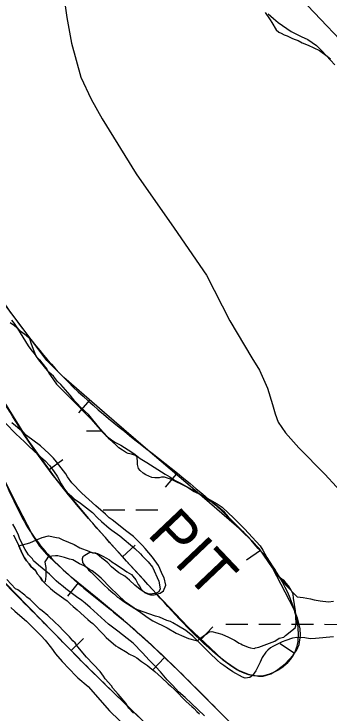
# Model space of a CAD drawing. Extents: x 3161665 to 3199565, y 885729 to 911164.
# Drawn here: x 3169915 to 3170375, y 908095 to 909117 of the extents above; entities that cross this region are included whole.
import ezdxf

# ---------------------------------------------------------------- set-up
doc = ezdxf.new("R2010")
doc.units = 0
for name, color, linetype in [('V-BORW-IDEN', 7, 'Continuous'), ('V-BORW-LINE', 7, 'Continuous'), ('V-ROAD-CNTR', 7, 'Continuous'), ('V-SITE-VEGE', 7, 'Continuous'), ('V-TOPO-SHOR', 7, 'Continuous'), ('V-WETL-SWMP', 7, 'Continuous')]:
    doc.layers.add(name, color=color, linetype=linetype)

msp = doc.modelspace()

# ---------------------------------------------------------------- linework, layer by layer
at = {"layer": 'V-BORW-LINE'}
for p, q in [((3170025.5, 908552.9), (3170009.1, 908534)), ((3169966.1, 908451.2), (3169986.3, 908465.8)), ((3170151.8, 908444.4), (3170135.6, 908425.4)), ((3170073.3, 908323.8), (3170091.7, 908340.7)), ((3170275.4, 908332.9), (3170254.7, 908318.9)), ((3170008.8, 908285.5), (3169993, 908266.1)), ((3170188.2, 908203.2), (3170205.3, 908221.5)), ((3169998.5, 908186.7), (3170016.3, 908204.3)), ((3170324.8, 908182.7), (3170304.1, 908196.8)), ((3170134.8, 908176.6), (3170117.6, 908158.4))]:
    msp.add_line(p, q, dxfattribs=at)
for points in [[(3170090.7, 909372.3), (3170106.4, 909355.4), (3170208.1, 909263.5), (3170306.2, 909169.4), (3170400.7, 909069.3), (3170470.9, 908965.6), (3170500.1, 908886.5)], [(3169901, 908549.2), (3169935.1, 908494), (3169977.4, 908435.4), (3170023.8, 908379.7), (3170072.8, 908324.3), (3170122.9, 908269.7), (3170169.1, 908221.2), (3170219.3, 908174), (3170231.7, 908164.7), (3170241.7, 908158.8), (3170257.1, 908152.4), (3170272.3, 908149.3), (3170278.9, 908149.4), (3170290.4, 908152.7), (3170298.8, 908157.4), (3170311.1, 908167.4), (3170322.9, 908179.9), (3170328.4, 908188), (3170331.5, 908195.5), (3170333.7, 908208.9), (3170333.1, 908219.1), (3170329.4, 908234), (3170323.7, 908247.7), (3170292.7, 908307.4), (3170273.8, 908335.2), (3170251, 908359.3), (3170179.1, 908421), (3170107.2, 908482.6), (3170047.2, 908534.1), (3169987.5, 908585.8), (3169962.6, 908610.7), (3169899.1, 908695.8)], [(3169635, 908635.7), (3169645.9, 908625.6), (3169656.9, 908615.4), (3169668.2, 908605.1), (3169679.4, 908594.8), (3169697.4, 908577), (3169714.8, 908558.7), (3169739.7, 908532.5), (3169763.2, 908505), (3169772.3, 908492), (3169794.6, 908450.3), (3169809, 908417.4), (3169823.9, 908384.8), (3169847.6, 908347.3), (3169875.7, 908313.1), (3169915.5, 908271.5), (3169955.7, 908230.2), (3169986.3, 908199.1), (3170017, 908168), (3170050, 908135.4), (3170083.4, 908103.1), (3170115.9, 908072)], [(3170236.6, 908075.6), (3170196, 908116.3), (3170155.4, 908157.1), (3170115.6, 908194.7), (3170074.8, 908231.2), (3170036.7, 908262.8), (3169998.2, 908294.1), (3169966.6, 908323.2), (3169952.6, 908339.2), (3169941.1, 908357), (3169920.6, 908396.4), (3169900.6, 908435.9)]]:
    msp.add_lwpolyline(points, dxfattribs=at)
msp.add_spline([(3169635, 908635.7), (3169656.9, 908615.4), (3169679.4, 908594.8), (3169714.8, 908558.7), (3169763.2, 908505), (3169794.6, 908450.3), (3169823.9, 908384.8), (3169875.7, 908313.1), (3169955.7, 908230.2), (3170017, 908168), (3170083.4, 908103.1), (3170148.4, 908040.9), (3170215.5, 907977.3), (3170279.4, 907917), (3170341.2, 907854.9), (3170400, 907770.9), (3170439.7, 907739.9), (3170508, 907690.1), (3170580.2, 907629.1), (3170645.4, 907571.8), (3170693.9, 907538.7), (3170708.2, 907548.5), (3170700.2, 907583.3), (3170658.1, 907634.1), (3170568.8, 907738.5), (3170460.8, 907856), (3170334.8, 907977.7), (3170236.6, 908075.6), (3170155.4, 908157.1), (3170074.8, 908231.2), (3169998.2, 908294.1), (3169941.1, 908357), (3169900.6, 908435.9), (3169854.3, 908528.6), (3169775.9, 908625.5), (3169707.6, 908700.2), (3169633.3, 908764.3), (3169562.8, 908823.2), (3169485.6, 908895.1), (3169433.8, 908951), (3169435, 908964.9), (3169466.6, 908949.7), (3169508.6, 908923.8), (3169592.2, 908864.6), (3169670.7, 908813.1), (3169732.3, 908792), (3169797.1, 908714.7), (3169867.2, 908604.4), (3169935.1, 908494), (3170023.8, 908379.7), (3170122.9, 908269.7), (3170219.3, 908174), (3170272.3, 908149.3), (3170322.9, 908179.9), (3170323.7, 908247.7), (3170251, 908359.3), (3170107.2, 908482.6), (3169987.5, 908585.8), (3169899.1, 908695.8), (3169830.3, 908793), (3169752.2, 908876.5), (3169658.4, 908949.8), (3169561.7, 909020), (3169502.5, 909070.4), (3169499.7, 909114.4), (3169564.7, 909165.2), (3169544.8, 909257.9), (3169487.8, 909300.9), (3169431.9, 909310.7), (3169381.8, 909274.8), (3169352.5, 909222.6), (3169310.5, 909208.1), (3169265.3, 909228.8), (3169246.1, 909212.1), (3169266.8, 909167.6), (3169325.2, 909091.6), (3169339.4, 909049), (3169296.2, 909043.8), (3169280, 909045.3), (3169313.9, 908970.3), (3169431.9, 908841.3), (3169538.1, 908732.9), (3169635, 908635.7)], degree=3, dxfattribs=at)
at = {"layer": 'V-ROAD-CNTR'}
msp.add_lwpolyline([(3169984.6, 909162.9), (3169991.9, 909111.8), (3169998.9, 909074.4), (3170012.3, 909024.4), (3170027.5, 908992.4), (3170043.7, 908963.8), (3170093.2, 908883.5), (3170149, 908804), (3170196.1, 908735.4), (3170230.3, 908668.6), (3170262.7, 908614.3), (3170273.8, 908596.7), (3170285.2, 908570.3), (3170292.5, 908546.3), (3170296.6, 908532.5), (3170300.9, 908520.7), (3170311.8, 908505.1), (3170331.4, 908482.8), (3170369.3, 908444.5), (3170403.3, 908407.6)], dxfattribs=at)
at = {"layer": 'V-SITE-VEGE'}
for p, q in [((3170286.4, 909117.2), (3170294.2, 909110.5)), ((3170294.2, 909110.5), (3170300.9, 909104.3)), ((3170300.9, 909104.3), (3170320, 909091.5)), ((3170320, 909091.5), (3170334.5, 909084.3)), ((3170334.5, 909084.3), (3170344.3, 909079.6)), ((3170344.3, 909079.6), (3170357.2, 909070.9)), ((3170357.2, 909070.9), (3170360.8, 909066.8)), ((3170360.8, 909066.8), (3170365, 909063.1)), ((3170365, 909063.1), (3170384.1, 909042.5)), ((3169915.3, 908661.3), (3169909.1, 908665.6)), ((3169920.6, 908656.9), (3169915.3, 908661.3)), ((3169925.4, 908652.6), (3169920.6, 908656.9)), ((3169932.5, 908647.2), (3169925.4, 908652.6)), ((3169937.8, 908642.4), (3169932.5, 908647.2)), ((3169940.1, 908634.7), (3169937.8, 908642.4)), ((3169946.7, 908617.9), (3169940.1, 908634.7)), ((3169951, 908611.7), (3169946.7, 908617.9)), ((3169965.8, 908593.8), (3169951, 908611.7)), ((3169972.5, 908587.5), (3169965.8, 908593.8)), ((3169978.2, 908579.8), (3169972.5, 908587.5)), ((3169983, 908575.5), (3169978.2, 908579.8)), ((3169996.8, 908560.1), (3169983, 908575.5)), ((3170003.9, 908551.4), (3169996.8, 908560.1)), ((3170006.8, 908548.5), (3170003.9, 908551.4)), ((3170012.5, 908541.8), (3170006.8, 908548.5)), ((3170024, 908531.1), (3170012.5, 908541.8)), ((3170030.2, 908523.9), (3170024, 908531.1)), ((3170040.6, 908510.9), (3170030.2, 908523.9)), ((3169902.1, 908518.9), (3169917.3, 908503.4)), ((3170051.6, 908499.3), (3170040.6, 908510.9)), ((3169917.3, 908503.4), (3169930.2, 908491.9)), ((3169930.2, 908491.9), (3169935.5, 908486.5)), ((3170054.5, 908495.5), (3170051.6, 908499.3)), ((3170063.5, 908487.3), (3170054.5, 908495.5)), ((3169935.5, 908486.5), (3169944, 908478.3)), ((3170067.8, 908482.9), (3170063.5, 908487.3)), ((3170073.6, 908479.5), (3170067.8, 908482.9)), ((3170079.3, 908475.7), (3170073.6, 908479.5)), ((3169944, 908478.3), (3169954.1, 908469.2)), ((3169954.1, 908469.2), (3169960.3, 908463.9)), ((3170081.7, 908474.7), (3170079.3, 908475.7)), ((3170086.5, 908473.7), (3170081.7, 908474.7)), ((3170092.2, 908471.8), (3170086.5, 908473.7)), ((3170094.6, 908469.4), (3170092.2, 908471.8)), ((3170095.5, 908462.2), (3170094.6, 908469.4)), ((3169960.3, 908463.9), (3169966.5, 908457.1)), ((3170095.5, 908458.8), (3170095.5, 908462.2)), ((3169966.5, 908457.1), (3169970.8, 908451.3)), ((3169970.8, 908451.3), (3169976.9, 908443.1)), ((3170096.9, 908453), (3170095.5, 908458.8)), ((3170099.3, 908450.1), (3170096.9, 908453)), ((3170103.6, 908445.8), (3170099.3, 908450.1)), ((3169976.9, 908443.1), (3169978.4, 908440.7)), ((3169978.4, 908440.7), (3169983.6, 908430.6)), ((3170107.4, 908443.4), (3170103.6, 908445.8)), ((3170116.5, 908439.5), (3170107.4, 908443.4)), ((3170120.8, 908439), (3170116.5, 908439.5)), ((3170127.1, 908439), (3170120.8, 908439)), ((3170130.4, 908439.9), (3170127.1, 908439)), ((3170134.7, 908439.9), (3170130.4, 908439.9)), ((3170144.8, 908436.9), (3170134.7, 908439.9)), ((3169983.6, 908430.6), (3169988.8, 908422.5)), ((3170166.8, 908425.8), (3170144.8, 908436.9)), ((3169988.8, 908422.5), (3169992.6, 908417.6)), ((3170174, 908421.4), (3170166.8, 908425.8)), ((3170177.3, 908419), (3170174, 908421.4)), ((3170185, 908415.6), (3170177.3, 908419)), ((3169992.6, 908417.6), (3169998.8, 908412.3)), ((3169998.8, 908412.3), (3170002.7, 908408.5)), ((3170002.7, 908408.5), (3170012.2, 908402.2)), ((3170192.6, 908410.3), (3170185, 908415.6)), ((3170206.5, 908402.1), (3170192.6, 908410.3)), ((3170012.2, 908402.2), (3170029.4, 908388.7)), ((3170222.7, 908389), (3170206.5, 908402.1)), ((3170029.4, 908388.7), (3170037, 908380.5)), ((3170226, 908385.2), (3170222.7, 908389)), ((3170037, 908380.5), (3170042.8, 908375.2)), ((3170231.3, 908378.4), (3170226, 908385.2)), ((3170232.7, 908376), (3170231.3, 908378.4)), ((3169916.6, 908365.8), (3169913.2, 908371.6)), ((3170042.8, 908375.2), (3170053.7, 908365.5)), ((3170239.9, 908369.3), (3170232.7, 908376)), ((3170248, 908361.1), (3170239.9, 908369.3)), ((3169921.3, 908355.2), (3169916.6, 908365.8)), ((3170053.7, 908365.5), (3170057.6, 908362.6)), ((3170057.6, 908362.6), (3170069.5, 908354.4)), ((3170261.3, 908348), (3170248, 908361.1)), ((3169923.2, 908349.4), (3169921.3, 908355.2)), ((3169931.3, 908334.5), (3169923.2, 908349.4)), ((3170069.5, 908354.4), (3170091.5, 908336)), ((3170266.1, 908342.7), (3170261.3, 908348)), ((3170271.8, 908336), (3170266.1, 908342.7)), ((3169936, 908326.8), (3169931.3, 908334.5)), ((3169941.7, 908320.6), (3169936, 908326.8)), ((3170025.7, 908330.2), (3170018.5, 908325.9)), ((3170033.9, 908329.2), (3170025.7, 908330.2)), ((3170036.3, 908327.7), (3170033.9, 908329.2)), ((3170043.4, 908321.9), (3170036.3, 908327.7)), ((3170091.5, 908336), (3170099.6, 908328.3)), ((3170099.6, 908328.3), (3170102, 908325.4)), ((3170283.3, 908324.4), (3170271.8, 908336)), ((3169943.2, 908318.1), (3169941.7, 908320.6)), ((3169950.8, 908311.4), (3169943.2, 908318.1)), ((3170015.6, 908323.5), (3170014.6, 908320.6)), ((3170014.6, 908320.6), (3170015.1, 908315.3)), ((3170018.5, 908325.9), (3170015.6, 908323.5)), ((3170049.2, 908317.6), (3170043.4, 908321.9)), ((3170052, 908315.1), (3170049.2, 908317.6)), ((3170102, 908325.4), (3170111, 908316.3)), ((3170111, 908316.3), (3170117.2, 908308.5)), ((3170293.3, 908308.5), (3170283.3, 908324.4)), ((3169966.5, 908298.4), (3169950.8, 908311.4)), ((3170015.1, 908315.3), (3170016.5, 908313.4)), ((3170016.5, 908313.4), (3170020.8, 908308.6)), ((3170020.8, 908308.6), (3170023.7, 908304.7)), ((3170057.3, 908308.9), (3170052, 908315.1)), ((3170068.2, 908300.2), (3170057.3, 908308.9)), ((3170117.2, 908308.5), (3170126.7, 908288.3)), ((3170294.7, 908306.1), (3170293.3, 908308.5)), ((3170297, 908301.3), (3170294.7, 908306.1)), ((3169976.6, 908288.7), (3169966.5, 908298.4)), ((3170023.7, 908304.7), (3170027.5, 908301.4)), ((3170027.5, 908301.4), (3170038.5, 908290.8)), ((3170076.9, 908295.3), (3170068.2, 908300.2)), ((3170299.9, 908297), (3170297, 908301.3)), ((3170301.8, 908294.6), (3170299.9, 908297)), ((3169980.4, 908285.3), (3169976.6, 908288.7)), ((3169986.6, 908280.5), (3169980.4, 908285.3)), ((3170038.5, 908290.8), (3170042.3, 908286.9)), ((3170042.3, 908286.9), (3170047, 908281.6)), ((3170083.5, 908289.5), (3170076.9, 908295.3)), ((3170091.2, 908282.3), (3170083.5, 908289.5)), ((3170126.7, 908288.3), (3170128.5, 908276.8)), ((3170306.6, 908291.2), (3170301.8, 908294.6)), ((3170309.5, 908289.7), (3170306.6, 908291.2)), ((3170312.8, 908285.4), (3170309.5, 908289.7)), ((3170316.1, 908281.5), (3170312.8, 908285.4)), ((3169990.4, 908277.1), (3169986.6, 908280.5)), ((3170006.2, 908265.5), (3169990.4, 908277.1)), ((3170047, 908281.6), (3170051.3, 908277.7)), ((3170051.3, 908277.7), (3170052.8, 908276.3)), ((3170052.8, 908276.3), (3170059.4, 908271)), ((3170099.3, 908276), (3170091.2, 908282.3)), ((3170103.1, 908273.6), (3170099.3, 908276)), ((3170128.5, 908276.8), (3170126.6, 908272.5)), ((3170319.4, 908276.2), (3170316.1, 908281.5)), ((3170322.8, 908269), (3170319.4, 908276.2)), ((3170013.8, 908259.7), (3170006.2, 908265.5)), ((3170059.4, 908271), (3170061.8, 908269)), ((3170061.8, 908269), (3170066.1, 908264.7)), ((3170105, 908272.2), (3170103.1, 908273.6)), ((3170112.2, 908269.2), (3170105, 908272.2)), ((3170121.8, 908270.1), (3170112.2, 908269.2)), ((3170126.6, 908272.5), (3170121.8, 908270.1)), ((3170323.2, 908263.3), (3170322.8, 908269)), ((3170018.6, 908255.9), (3170013.8, 908259.7)), ((3170026.2, 908249.6), (3170018.6, 908255.9)), ((3170066.1, 908264.7), (3170069.5, 908262.8)), ((3170069.5, 908262.8), (3170075.2, 908258.4)), ((3170075.2, 908258.4), (3170096.7, 908244.9)), ((3170326.5, 908245), (3170323.2, 908263.3)), ((3169910.2, 908249.7), (3169915.9, 908244.4)), ((3169915.9, 908244.4), (3169923.5, 908238.2)), ((3170053, 908225.4), (3170026.2, 908249.6)), ((3170096.7, 908244.9), (3170111, 908234.7)), ((3170326.9, 908239.3), (3170326.5, 908245)), ((3169923.5, 908238.2), (3169933.1, 908229.9)), ((3170111, 908234.7), (3170117.7, 908230.4)), ((3170326.9, 908234.9), (3170326.9, 908239.3)), ((3170327.3, 908227.3), (3170326.9, 908234.9)), ((3169933.1, 908229.9), (3169954.5, 908208.2)), ((3170066.8, 908215.3), (3170053, 908225.4)), ((3170117.7, 908230.4), (3170138.8, 908220.2)), ((3170326.8, 908223), (3170327.3, 908227.3)), ((3170080.2, 908204.2), (3170066.8, 908215.3)), ((3170138.8, 908220.2), (3170151.7, 908212.4)), ((3170197.7, 908212.2), (3170200.2, 908214.1)), ((3170200.2, 908214.1), (3170204, 908214.5)), ((3170204, 908214.5), (3170218.4, 908210.6)), ((3170311.9, 908208.7), (3170325.9, 908220.1)), ((3170325.9, 908220.1), (3170326.8, 908223)), ((3169954.5, 908208.2), (3169960.3, 908202)), ((3170088.8, 908197.4), (3170080.2, 908204.2)), ((3170151.7, 908212.4), (3170163.2, 908207.1)), ((3170163.2, 908207.1), (3170169.9, 908204.6)), ((3170169.9, 908204.6), (3170180.9, 908201.7)), ((3170183.8, 908201.7), (3170185.2, 908203.6)), ((3170185.2, 908203.6), (3170197.7, 908212.2)), ((3170218.4, 908210.6), (3170228.4, 908206.2)), ((3170228.4, 908206.2), (3170237, 908201.9)), ((3170296, 908200.6), (3170302.7, 908204.9)), ((3170302.7, 908204.9), (3170309.5, 908206.3)), ((3170309.5, 908206.3), (3170311.9, 908208.7)), ((3169960.3, 908202), (3169969.8, 908190.4)), ((3170102.6, 908183.4), (3170088.8, 908197.4)), ((3170180.9, 908201.7), (3170183.8, 908201.7)), ((3170237, 908201.9), (3170244.2, 908197.5)), ((3170244.2, 908197.5), (3170246.6, 908196.5)), ((3170246.6, 908196.5), (3170249, 908195.1)), ((3170249, 908195.1), (3170257.1, 908191.7)), ((3170272.9, 908191.6), (3170296, 908200.6)), ((3169969.8, 908190.4), (3169975.5, 908182.2)), ((3170112.6, 908172.8), (3170102.6, 908183.4)), ((3170257.1, 908191.7), (3170260.5, 908190.7)), ((3170260.5, 908190.7), (3170265.7, 908189.7)), ((3170265.7, 908189.7), (3170268.1, 908190.7)), ((3170268.1, 908190.7), (3170272.9, 908191.6)), ((3169975.5, 908182.2), (3169985, 908170.7)), ((3169985, 908170.7), (3170005.5, 908149.4)), ((3170122.2, 908163.2), (3170112.6, 908172.8)), ((3170128.8, 908155.9), (3170122.2, 908163.2)), ((3170138.8, 908143.9), (3170128.8, 908155.9)), ((3170005.5, 908149.4), (3170007.9, 908147)), ((3170007.9, 908147), (3170023.2, 908134)), ((3170147, 908135.7), (3170138.8, 908143.9)), ((3170023.2, 908134), (3170054.2, 908098.8)), ((3170155.5, 908126.5), (3170147, 908135.7)), ((3170165.1, 908118.3), (3170155.5, 908126.5)), ((3170193.2, 908091.3), (3170165.1, 908118.3)), ((3170054.2, 908098.8), (3170111.4, 908044.3))]:
    msp.add_line(p, q, dxfattribs=at)
at = {"layer": 'V-TOPO-SHOR'}
for points in [[(3170282, 909118.9), (3170289.3, 909108.6), (3170291.6, 909104.5), (3170298, 909093.8), (3170302.2, 909090.5), (3170305.4, 909088.7), (3170310, 909086.3), (3170314.2, 909084.9), (3170322, 909081.2), (3170325.7, 909079.7), (3170330.3, 909078.3), (3170336.3, 909074.6), (3170344.7, 909071.3), (3170353.4, 909067.6), (3170361.3, 909063.8), (3170372.8, 909055.4), (3170377.4, 909051.2)], [(3169913.9, 908355.7), (3169921.8, 908339.6)], [(3169921.8, 908339.6), (3169926.7, 908328.8), (3169929.9, 908322.3), (3169933.1, 908317.7), (3169936.8, 908313.5), (3169940, 908309.3), (3169942.3, 908307), (3169946, 908303.7), (3169949.2, 908298.6), (3169952.9, 908294), (3169956.6, 908288.8), (3169958.8, 908286.3)], [(3170089.3, 908095.1), (3170082.8, 908102.5), (3170078.2, 908110), (3170067.2, 908123), (3170059.4, 908131.8), (3170057.1, 908135.1), (3170047.9, 908145.3), (3170045.6, 908149.5), (3170040.5, 908156), (3170020.7, 908176.9), (3170008.3, 908192.3), (3170004.2, 908197.9), (3170001, 908201.1), (3169995.9, 908206.7), (3169987.2, 908215.5), (3169980.3, 908223), (3169974.7, 908227.6), (3169964.1, 908237.9), (3169955.8, 908244.9), (3169952.6, 908247.2), (3169949.9, 908249.5), (3169938.3, 908261.6), (3169933.7, 908264.9), (3169930.5, 908267.7), (3169920.4, 908275.6), (3169917.1, 908277), (3169904.3, 908290.5)], [(3169958.8, 908286.3), (3169960.2, 908284.7), (3169968.1, 908277.2), (3169974.1, 908272.5), (3169984.2, 908265.5), (3169987.4, 908262.8), (3169992.5, 908259.5), (3169997.1, 908254.8), (3170001.2, 908251.1), (3170004, 908248.8), (3170007.2, 908246.4), (3170022.9, 908232), (3170026.6, 908228.7), (3170029.8, 908226.4), (3170033.5, 908223.1), (3170041.8, 908214.3), (3170045.5, 908210.1), (3170049.6, 908205.9), (3170063.4, 908193.8), (3170067.1, 908191.5), (3170080, 908184), (3170082.8, 908182.1), (3170091.1, 908177.9), (3170094.3, 908176.1), (3170101.3, 908170.9), (3170110, 908164.9), (3170113.7, 908161.6), (3170117.8, 908158.8), (3170120.6, 908156), (3170130.3, 908147.2), (3170140.4, 908138.3), (3170143.6, 908135), (3170149.2, 908129.9), (3170166.7, 908112.2), (3170174.9, 908105.2), (3170178.2, 908102), (3170181.9, 908097.8), (3170186, 908094.1)]]:
    msp.add_lwpolyline(points, dxfattribs=at)
at = {"layer": 'V-WETL-SWMP'}
for p, q in [((3170020.7, 908508), (3170042.4, 908508)), ((3170058.7, 908492.5), (3170060.6, 908492.5)), ((3170045, 908392.5), (3170077, 908392.4)), ((3170093, 908392.4), (3170125, 908392.3)), ((3170224.6, 908225.5), (3170256.6, 908225.4)), ((3170272.6, 908225.4), (3170304.6, 908225.3)), ((3170320.6, 908225.3), (3170352.6, 908225.2)), ((3170368.6, 908225.1), (3170400.6, 908225))]:
    msp.add_line(p, q, dxfattribs=at)
for points in [[(3169911.3, 908669.6), (3169915, 908664.9), (3169920, 908657.5), (3169935.6, 908631.9), (3169940.7, 908624.5), (3169944.3, 908620.8), (3169947.6, 908616.1), (3169952.2, 908611.5), (3169962.7, 908598), (3169965.9, 908591.9), (3169972.4, 908582.2), (3169977, 908576.1), (3169987.6, 908565.4), (3170007.8, 908545.4), (3170016.6, 908536.1), (3170027.1, 908525.4), (3170044.6, 908505.4), (3170049.7, 908500.7), (3170057.5, 908494.7), (3170062.1, 908491.4), (3170070.9, 908486.7), (3170087, 908476.5), (3170092.1, 908473.2), (3170099, 908467.6), (3170109.2, 908461.5), (3170135.9, 908444.3), (3170142.4, 908440.5), (3170149.3, 908435.8), (3170158.1, 908431.6), (3170188.1, 908414.8), (3170211.6, 908401.2), (3170219, 908396.1), (3170236, 908380.3), (3170251.7, 908364.5), (3170274.7, 908339.8), (3170278.4, 908333.3), (3170281.6, 908328.2), (3170284.3, 908322.6), (3170293, 908309.1), (3170296.2, 908305.4), (3170303.6, 908292.4), (3170312.3, 908282.2), (3170328.9, 908265.4), (3170337.7, 908264.5), (3170348.3, 908262.5), (3170353.9, 908261.1)], [(3169916.8, 908515.1), (3169911.7, 908519.7)], [(3170127.4, 908235.5), (3170121.8, 908237), (3170111.7, 908240.3), (3170105.2, 908243.1), (3170095.5, 908246.4), (3170090.4, 908248.7), (3170083.9, 908252.9), (3170078, 908257.6), (3170066, 908268.7), (3170055.9, 908278.5), (3170042, 908292.5), (3170036.1, 908298.1), (3170029.1, 908303.2), (3170025, 908305.1), (3170017.1, 908310.7), (3170010.7, 908313.5), (3170001, 908319.1), (3169995.9, 908320.5), (3169988.5, 908322.9), (3169978.8, 908325.2), (3169975.6, 908325.3), (3169970, 908324.8), (3169966.8, 908324.4), (3169963.5, 908322.1), (3169959.8, 908316.6), (3169960.2, 908312.8), (3169961.1, 908308.2), (3169961.1, 908295.7), (3169960.1, 908287.8), (3169958.8, 908286.3), (3169956.6, 908288.8), (3169952.9, 908294), (3169949.2, 908298.6), (3169946, 908303.7), (3169942.3, 908307), (3169940, 908309.3), (3169936.8, 908313.5), (3169933.1, 908317.7), (3169929.9, 908322.3), (3169926.7, 908328.8), (3169921.8, 908339.6), (3169938.1, 908344.1), (3169947.8, 908348.7), (3169955.7, 908351.9), (3169965.4, 908354.6), (3169977, 908351.8), (3169980.2, 908351.3), (3169986.2, 908348.5), (3170002.9, 908341.5), (3170011.2, 908336.8), (3170024.1, 908332.1), (3170029.6, 908329.7), (3170036.6, 908328.8), (3170045.8, 908324.1), (3170049, 908322.2), (3170054.6, 908319.4), (3170057.8, 908316.6), (3170064.3, 908312.4), (3170076.3, 908304), (3170079.9, 908301.7), (3170086.4, 908297.9), (3170088.7, 908295.6), (3170092.8, 908290), (3170096.5, 908283.5), (3170098.8, 908280.3), (3170100.2, 908277), (3170105.7, 908271.4), (3170109.9, 908269.6), (3170114.5, 908268.2), (3170119.6, 908268.1), (3170128.4, 908270.4), (3170133.5, 908274.1), (3170136.8, 908282.4), (3170134.1, 908293), (3170131.3, 908298.6), (3170128.1, 908306.5), (3170125.8, 908311.1), (3170117.1, 908323.2), (3170106.5, 908335.8), (3170102.8, 908340.4), (3170095.9, 908347), (3170089.5, 908353.5), (3170079.8, 908360.5), (3170058.1, 908377.7), (3170054, 908380.5), (3170048.5, 908386.1), (3170034.2, 908398.2), (3170013.9, 908416.8), (3169999.2, 908431.7), (3169992.8, 908440.6), (3169990.5, 908444.8), (3169976.7, 908462.4), (3169972.5, 908468), (3169965.2, 908475.4), (3169960.1, 908479.6), (3169953.7, 908485.7), (3169932.9, 908501.1), (3169929.7, 908504.3), (3169925.6, 908507.6), (3169923.3, 908509.9), (3169916.8, 908515.1)], [(3170353.9, 908261.1), (3170362.6, 908259.2), (3170374.7, 908257.8), (3170382.1, 908259.1)], [(3170381.8, 908206.8), (3170355.4, 908204.2), (3170348, 908203.8), (3170340.1, 908205.2), (3170328.1, 908205.7), (3170322.1, 908204.8), (3170312.3, 908201.6), (3170306.8, 908199.4), (3170293.3, 908192.9), (3170289.6, 908190.7), (3170285.9, 908187.4), (3170283.1, 908184.2), (3170277.5, 908176.8), (3170274.7, 908169.9), (3170270.9, 908162.1), (3170268.6, 908157), (3170263.4, 908150.1), (3170259.7, 908147.3), (3170252.8, 908146.4), (3170249.1, 908147.8), (3170234.8, 908155.8), (3170226.9, 908160.9), (3170221.4, 908165.1), (3170217.3, 908167.9), (3170211.7, 908172.6), (3170201.1, 908182.8), (3170176.3, 908208), (3170166.1, 908215.9), (3170155.5, 908222.4), (3170147.2, 908227.1), (3170143.5, 908229), (3170138, 908230.8), (3170127.4, 908235.5)]]:
    msp.add_lwpolyline(points, dxfattribs=at)

# ---------------------------------------------------------------- texts
at = {"layer": 'V-BORW-IDEN'}
msp.add_text('PIT', height=64, rotation=313.4926, dxfattribs=at).set_placement((3170108, 908355.9))

doc.saveas('drawing.dxf')
